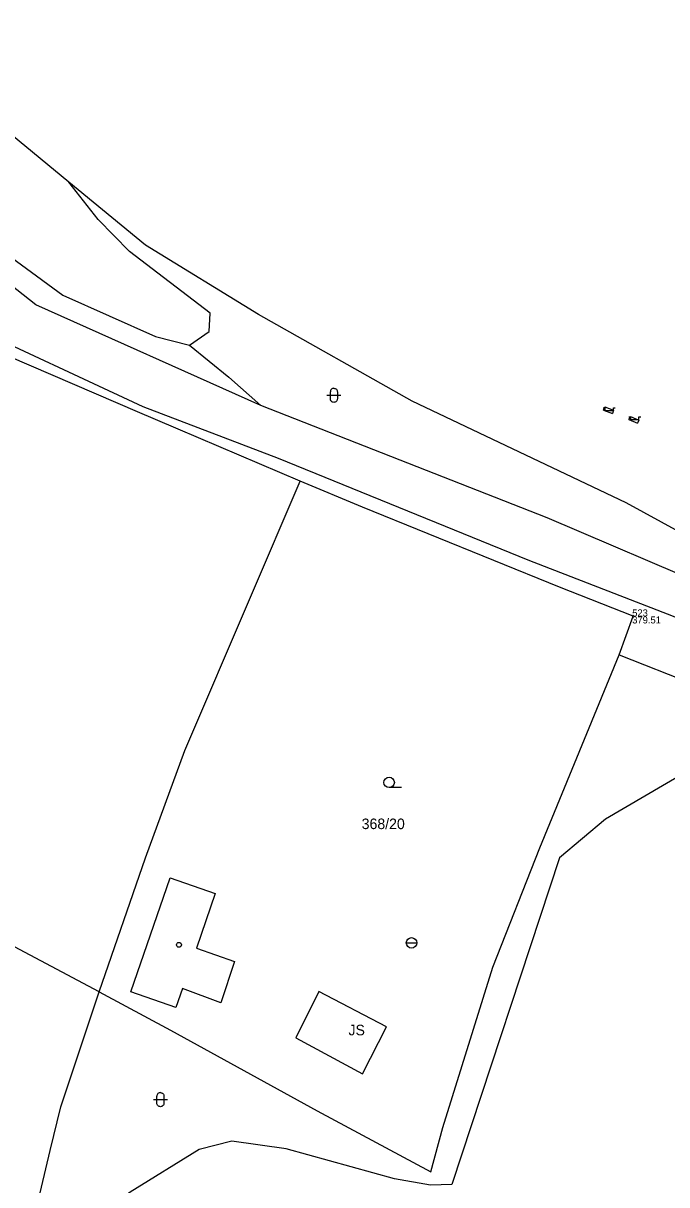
# Model space of a CAD drawing. Extents: x -836739 to -835945, y -1070775 to -1070126.
# Drawn here: x -836413.1 to -836367.3, y -1070448 to -1070365.3 of the extents above; entities that cross this region are included whole.
import ezdxf

# ---------------------------------------------------------------- set-up
doc = ezdxf.new("R2010")
doc.units = 0
for name, color, linetype in [('BodPole_mer', 7, 'Continuous'), ('BodPole_popis', 7, 'Continuous'), ('Budovy_hranice', 7, 'Continuous'), ('Budovy_kody', 7, 'Continuous'), ('Doprava_hranice', 7, 'Continuous'), ('OstPloch_hranice', 7, 'Continuous'), ('OstPloch_kody', 7, 'Continuous'), ('PovrZnIS_hranice', 7, 'Continuous'), ('PovrZnIS_kody', 7, 'Continuous'), ('RuianPar_popis', 7, 'Continuous'), ('Stavby_hr_stav', 7, 'Continuous'), ('Stavby_kody', 7, 'Continuous'), ('Stavby_linie', 7, 'Continuous'), ('Vodstvo_body', 7, 'Continuous')]:
    doc.layers.add(name, color=color, linetype=linetype)

msp = doc.modelspace()

# ---------------------------------------------------------------- linework, layer by layer
at = {"layer": 'BodPole_mer'}
for p, q in [((-836409.87, -1070376.61), (-836409.87, -1070376.61)), ((-836407.8, -1070379.27), (-836407.8, -1070379.27)), ((-836404.41, -1070381.11), (-836404.41, -1070381.11)), ((-836405.57, -1070381.55), (-836405.57, -1070381.55)), ((-836412.22, -1070385.35), (-836412.22, -1070385.35)), ((-836410.31, -1070384.67), (-836410.31, -1070384.67)), ((-836399.82, -1070385.94), (-836399.82, -1070385.94)), ((-836396.38, -1070386.03), (-836396.38, -1070386.03)), ((-836403.72, -1070387.61), (-836403.72, -1070387.61)), ((-836399.88, -1070387.24), (-836399.88, -1070387.24)), ((-836401.28, -1070388.23), (-836401.28, -1070388.23)), ((-836398.49, -1070390.5), (-836398.49, -1070390.5)), ((-836404.61, -1070392.58), (-836404.61, -1070392.58)), ((-836396.2, -1070392.51), (-836396.2, -1070392.51)), ((-836385.43, -1070392.2), (-836385.43, -1070392.2)), ((-836371.81, -1070392.85), (-836371.81, -1070392.85)), ((-836371.81, -1070392.85), (-836371.81, -1070392.85)), ((-836371.72, -1070392.62), (-836371.72, -1070392.62)), ((-836371.72, -1070392.62), (-836371.72, -1070392.62)), ((-836371.09, -1070392.85), (-836371.09, -1070392.85)), ((-836371.09, -1070392.85), (-836371.09, -1070392.85)), ((-836405, -1070392.97), (-836405, -1070392.97)), ((-836371.18, -1070393.08), (-836371.18, -1070393.08)), ((-836371.18, -1070393.08), (-836371.18, -1070393.08)), ((-836370, -1070393.52), (-836370, -1070393.52)), ((-836370, -1070393.52), (-836370, -1070393.52)), ((-836369.9, -1070393.29), (-836369.9, -1070393.29)), ((-836369.9, -1070393.29), (-836369.9, -1070393.29)), ((-836369.29, -1070393.55), (-836369.29, -1070393.55)), ((-836369.29, -1070393.55), (-836369.29, -1070393.55)), ((-836369.39, -1070393.78), (-836369.39, -1070393.78)), ((-836369.39, -1070393.78), (-836369.39, -1070393.78)), ((-836394.98, -1070396.26), (-836394.98, -1070396.26)), ((-836393.4, -1070397.9), (-836393.4, -1070397.9)), ((-836370.19, -1070399.44), (-836370.19, -1070399.44)), ((-836388.98, -1070399.76), (-836388.98, -1070399.76)), ((-836375.83, -1070400.5), (-836375.83, -1070400.5)), ((-836377.21, -1070403.49), (-836377.21, -1070403.49)), ((-836396.94, -1070406.16), (-836396.94, -1070406.16)), ((-836374.95, -1070405.45), (-836374.95, -1070405.45)), ((-836369.77, -1070407.53), (-836369.77, -1070407.53)), ((-836369.71, -1070407.51), (-836369.71, -1070407.51)), ((-836370.7, -1070410.27), (-836370.7, -1070410.27)), ((-836401.63, -1070417.07), (-836401.63, -1070417.07)), ((-836371.68, -1070421.97), (-836371.68, -1070421.97)), ((-836376.35, -1070424), (-836376.35, -1070424)), ((-836404.42, -1070424.71), (-836404.42, -1070424.71)), ((-836374.95, -1070424.71), (-836374.95, -1070424.71)), ((-836402.66, -1070426.14), (-836402.66, -1070426.14)), ((-836399.46, -1070427.25), (-836399.46, -1070427.25)), ((-836385.48, -1070430.77), (-836385.48, -1070430.77)), ((-836400.8, -1070431.15), (-836400.8, -1070431.15)), ((-836398.08, -1070432.09), (-836398.08, -1070432.09)), ((-836379.69, -1070432.5), (-836379.69, -1070432.5)), ((-836407.72, -1070434.26), (-836407.72, -1070434.26)), ((-836405.46, -1070434.26), (-836405.46, -1070434.26)), ((-836401.78, -1070434.02), (-836401.78, -1070434.02)), ((-836392.07, -1070434.23), (-836392.07, -1070434.23)), ((-836399.05, -1070435.03), (-836399.05, -1070435.03)), ((-836402.26, -1070435.37), (-836402.26, -1070435.37)), ((-836387.27, -1070436.75), (-836387.27, -1070436.75)), ((-836402.65, -1070436.98), (-836402.65, -1070436.98)), ((-836393.73, -1070437.54), (-836393.73, -1070437.54)), ((-836388.97, -1070440.09), (-836388.97, -1070440.09)), ((-836410.44, -1070442.44), (-836410.44, -1070442.44)), ((-836392.21, -1070442.72), (-836392.21, -1070442.72)), ((-836383.25, -1070443.91), (-836383.25, -1070443.91)), ((-836398.28, -1070444.88), (-836398.28, -1070444.88)), ((-836411.22, -1070445.56), (-836411.22, -1070445.56)), ((-836400.59, -1070445.48), (-836400.59, -1070445.48)), ((-836394.4, -1070445.42), (-836394.4, -1070445.42)), ((-836384.11, -1070447.06), (-836384.11, -1070447.06)), ((-836386.69, -1070447.56), (-836386.69, -1070447.56)), ((-836382.62, -1070447.97), (-836382.62, -1070447.97))]:
    msp.add_line(p, q, dxfattribs=at)
at = {"layer": 'Budovy_hranice'}
for p, q in [((-836405.46, -1070434.26), (-836402.66, -1070426.14)), ((-836402.66, -1070426.14), (-836399.46, -1070427.25)), ((-836399.46, -1070427.25), (-836400.8, -1070431.15)), ((-836400.8, -1070431.15), (-836398.08, -1070432.09)), ((-836398.08, -1070432.09), (-836399.05, -1070435.03)), ((-836402.26, -1070435.37), (-836405.46, -1070434.26)), ((-836401.78, -1070434.02), (-836402.26, -1070435.37)), ((-836399.05, -1070435.03), (-836401.78, -1070434.02))]:
    msp.add_line(p, q, dxfattribs=at)
at = {"layer": 'Budovy_kody'}
msp.add_circle((-836402.04, -1070430.91), 0.175, dxfattribs=at)
at = {"layer": 'Doprava_hranice'}
for points in [[(-836490.91, -1070321.78), (-836479.74, -1070331.15), (-836472.55, -1070338.03), (-836463.6, -1070345.51), (-836457.27, -1070350.28), (-836449.01, -1070356.39), (-836440.87, -1070363.54), (-836429.17, -1070372.36), (-836419.16, -1070378.17), (-836410.31, -1070384.67), (-836403.72, -1070387.61), (-836401.28, -1070388.23), (-836398.49, -1070390.5), (-836396.2, -1070392.51)], [(-836363.94, -1070405.58), (-836375.83, -1070400.5), (-836396.2, -1070392.51), (-836412.22, -1070385.35), (-836415.3, -1070382.95)], [(-836417.67, -1070386.5), (-836404.61, -1070392.58), (-836394.98, -1070396.26), (-836377.21, -1070403.49), (-836366.86, -1070407.51), (-836361.89, -1070409.63)], [(-836370.7, -1070410.27), (-836360.12, -1070414.44), (-836352.3, -1070417.49), (-836345.8, -1070420.64)]]:
    msp.add_lwpolyline(points, dxfattribs=at)
at = {"layer": 'OstPloch_hranice'}
for points in [[(-836356.62, -1070406.87), (-836370.19, -1070399.44), (-836385.43, -1070392.2), (-836396.38, -1070386.03), (-836404.41, -1070381.11), (-836409.87, -1070376.61), (-836425.28, -1070363.93), (-836449.03, -1070345.44), (-836455, -1070340), (-836462.64, -1070329.11), (-836464.81, -1070325.47), (-836465.74, -1070321.03), (-836464.89, -1070314.87), (-836461.62, -1070306.74), (-836456.41, -1070297.54), (-836450.95, -1070288.2), (-836447.03, -1070272.79), (-836441.38, -1070260.76)], [(-836401.28, -1070388.23), (-836399.88, -1070387.24), (-836399.82, -1070385.94), (-836405.57, -1070381.55), (-836407.8, -1070379.27), (-836409.87, -1070376.61)], [(-836345.8, -1070420.64), (-836355.7, -1070417.34), (-836361.05, -1070417.62), (-836366.07, -1070418.7), (-836371.68, -1070421.97), (-836374.95, -1070424.71), (-836382.62, -1070447.97)], [(-836382.62, -1070447.97), (-836384.12, -1070448.01), (-836386.69, -1070447.56), (-836394.4, -1070445.42), (-836398.28, -1070444.88), (-836400.59, -1070445.48), (-836405.51, -1070448.52), (-836410.77, -1070452.46), (-836414.78, -1070467.48), (-836419.92, -1070491.57), (-836422.14, -1070507.07), (-836424.43, -1070527.13), (-836426.86, -1070555.21), (-836427.73, -1070571.17), (-836426.62, -1070578.67)]]:
    msp.add_lwpolyline(points, dxfattribs=at)
at = {"layer": 'OstPloch_kody'}
for p, q in [((-836391.51, -1070391.79), (-836390.51, -1070391.79)), ((-836391.26, -1070392.04), (-836391.26, -1070391.54)), ((-836390.76, -1070391.54), (-836390.76, -1070392.04)), ((-836386.205, -1070419.72), (-836387.08, -1070419.72)), ((-836403.61, -1070442.18), (-836403.61, -1070441.68)), ((-836403.11, -1070441.68), (-836403.11, -1070442.18)), ((-836403.86, -1070441.93), (-836402.86, -1070441.93))]:
    msp.add_line(p, q, dxfattribs=at)
for points in [[(-836391.01, -1070391.29), (-836391.055, -1070391.294), (-836391.102, -1070391.308), (-836391.147, -1070391.331), (-836391.187, -1070391.363), (-836391.219, -1070391.403), (-836391.242, -1070391.448), (-836391.256, -1070391.495), (-836391.26, -1070391.54)], [(-836391.01, -1070392.29), (-836391.055, -1070392.286), (-836391.102, -1070392.272), (-836391.147, -1070392.249), (-836391.187, -1070392.217), (-836391.219, -1070392.177), (-836391.242, -1070392.132), (-836391.256, -1070392.085), (-836391.26, -1070392.04)], [(-836391.01, -1070391.29), (-836390.965, -1070391.294), (-836390.918, -1070391.308), (-836390.873, -1070391.331), (-836390.833, -1070391.363), (-836390.801, -1070391.403), (-836390.778, -1070391.448), (-836390.764, -1070391.495), (-836390.76, -1070391.54)], [(-836390.76, -1070392.04), (-836390.764, -1070392.085), (-836390.778, -1070392.132), (-836390.801, -1070392.177), (-836390.833, -1070392.217), (-836390.873, -1070392.249), (-836390.918, -1070392.272), (-836390.965, -1070392.286), (-836391.01, -1070392.29)], [(-836403.36, -1070441.43), (-836403.405, -1070441.434), (-836403.452, -1070441.448), (-836403.497, -1070441.471), (-836403.537, -1070441.503), (-836403.569, -1070441.543), (-836403.592, -1070441.588), (-836403.606, -1070441.635), (-836403.61, -1070441.68)], [(-836403.36, -1070441.43), (-836403.315, -1070441.434), (-836403.268, -1070441.448), (-836403.223, -1070441.471), (-836403.183, -1070441.503), (-836403.151, -1070441.543), (-836403.128, -1070441.588), (-836403.114, -1070441.635), (-836403.11, -1070441.68)], [(-836403.36, -1070442.43), (-836403.405, -1070442.426), (-836403.452, -1070442.412), (-836403.497, -1070442.389), (-836403.537, -1070442.357), (-836403.569, -1070442.317), (-836403.592, -1070442.272), (-836403.606, -1070442.225), (-836403.61, -1070442.18)], [(-836403.11, -1070442.18), (-836403.114, -1070442.225), (-836403.128, -1070442.272), (-836403.151, -1070442.317), (-836403.183, -1070442.357), (-836403.223, -1070442.389), (-836403.268, -1070442.412), (-836403.315, -1070442.426), (-836403.36, -1070442.43)]]:
    msp.add_lwpolyline(points, dxfattribs=at)
msp.add_ellipse((-836387.08, -1070419.345), major_axis=(0.375, 0), ratio=0.999999, dxfattribs=at)
at = {"layer": 'PovrZnIS_hranice'}
for p, q in [((-836371.81, -1070392.85), (-836371.18, -1070393.08)), ((-836371.81, -1070392.85), (-836371.18, -1070393.08)), ((-836370, -1070393.52), (-836369.39, -1070393.78)), ((-836370, -1070393.52), (-836369.39, -1070393.78))]:
    msp.add_line(p, q, dxfattribs=at)
for points in [[(-836371.81, -1070392.85), (-836371.72, -1070392.62), (-836371.09, -1070392.85), (-836371.18, -1070393.08)], [(-836371.81, -1070392.85), (-836371.72, -1070392.62), (-836371.09, -1070392.85), (-836371.18, -1070393.08)], [(-836370, -1070393.52), (-836369.9, -1070393.29), (-836369.29, -1070393.55), (-836369.39, -1070393.78)], [(-836370, -1070393.52), (-836369.9, -1070393.29), (-836369.29, -1070393.55), (-836369.39, -1070393.78)]]:
    msp.add_lwpolyline(points, dxfattribs=at)
at = {"layer": 'PovrZnIS_kody'}
for p, q in [((-836371.831, -1070392.68), (-836371.71, -1070392.68)), ((-836371.831, -1070392.68), (-836371.71, -1070392.68)), ((-836371.71, -1070392.68), (-836371.71, -1070392.88)), ((-836371.71, -1070392.68), (-836371.71, -1070392.88)), ((-836371.71, -1070392.88), (-836371.11, -1070392.88)), ((-836371.71, -1070392.88), (-836371.11, -1070392.88)), ((-836371.11, -1070392.88), (-836371.11, -1070392.68)), ((-836371.11, -1070392.68), (-836370.976, -1070392.68)), ((-836371.11, -1070392.88), (-836371.11, -1070392.68)), ((-836371.11, -1070392.68), (-836370.976, -1070392.68)), ((-836370.021, -1070393.32), (-836369.9, -1070393.32)), ((-836370.021, -1070393.32), (-836369.9, -1070393.32)), ((-836369.9, -1070393.32), (-836369.9, -1070393.52)), ((-836369.9, -1070393.32), (-836369.9, -1070393.52)), ((-836369.9, -1070393.52), (-836369.3, -1070393.52)), ((-836369.9, -1070393.52), (-836369.3, -1070393.52)), ((-836369.3, -1070393.52), (-836369.3, -1070393.32)), ((-836369.3, -1070393.32), (-836369.166, -1070393.32)), ((-836369.3, -1070393.52), (-836369.3, -1070393.32)), ((-836369.3, -1070393.32), (-836369.166, -1070393.32))]:
    msp.add_line(p, q, dxfattribs=at)
at = {"layer": 'RuianPar_popis'}
msp.add_line((-836389.03, -1070422.67), (-836389.03, -1070422.67), dxfattribs=at)
at = {"layer": 'Stavby_hr_stav'}
msp.add_lwpolyline([(-836387.27, -1070436.75), (-836392.07, -1070434.23), (-836393.73, -1070437.54), (-836388.97, -1070440.09), (-836387.27, -1070436.75)], dxfattribs=at)
at = {"layer": 'Stavby_linie'}
for points in [[(-836393.4, -1070397.9), (-836405, -1070392.97), (-836414.08, -1070389.04), (-836418.22, -1070387.23), (-836418.59, -1070387.07)], [(-836407.72, -1070434.26), (-836404.42, -1070424.71), (-836401.63, -1070417.07), (-836396.94, -1070406.16), (-836393.4, -1070397.9)], [(-836369.71, -1070407.51), (-836374.95, -1070405.45), (-836388.98, -1070399.76), (-836393.4, -1070397.9)], [(-836407.72, -1070434.26), (-836402.65, -1070436.98), (-836392.21, -1070442.72), (-836384.11, -1070447.06), (-836383.25, -1070443.91), (-836379.69, -1070432.5), (-836376.35, -1070424), (-836370.7, -1070410.27), (-836369.71, -1070407.51)], [(-836407.72, -1070434.26), (-836415.3, -1070430.25), (-836428, -1070423.55), (-836445.87, -1070414.08), (-836449.39, -1070412.25)], [(-836427.9, -1070546.1), (-836426.76, -1070535.49), (-836425.46, -1070522.59), (-836424.54, -1070513.97), (-836423.07, -1070499.04), (-836421.63, -1070492.15), (-836418.84, -1070478.02), (-836414.08, -1070457.69), (-836411.22, -1070445.56), (-836410.44, -1070442.44), (-836407.72, -1070434.26)]]:
    msp.add_lwpolyline(points, dxfattribs=at)
at = {"layer": 'Vodstvo_body'}
msp.add_line((-836385.855, -1070430.77), (-836385.105, -1070430.77), dxfattribs=at)
msp.add_circle((-836385.48, -1070430.77), 0.375, dxfattribs=at)

# ---------------------------------------------------------------- texts
at = {"layer": 'BodPole_popis'}
for s, p in [('379.51', (-836369.77, -1070408.03)), ('523', (-836369.77, -1070407.53))]:
    msp.add_text(s, height=0.5, dxfattribs=at).set_placement(p)
at = {"layer": 'RuianPar_popis'}
msp.add_text('368/20', height=0.75, dxfattribs=at).set_placement((-836389.03, -1070422.67))
at = {"layer": 'Stavby_kody'}
msp.add_text('JS', height=0.75, dxfattribs=at).set_placement((-836389.97, -1070437.35))

doc.saveas('drawing.dxf')
